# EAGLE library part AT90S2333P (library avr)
MICROCONTROLLER 2 Kbytes FLASH 128 bytes SRAM 128 bytes EEPROM UART 6-channel 10-bit ADC
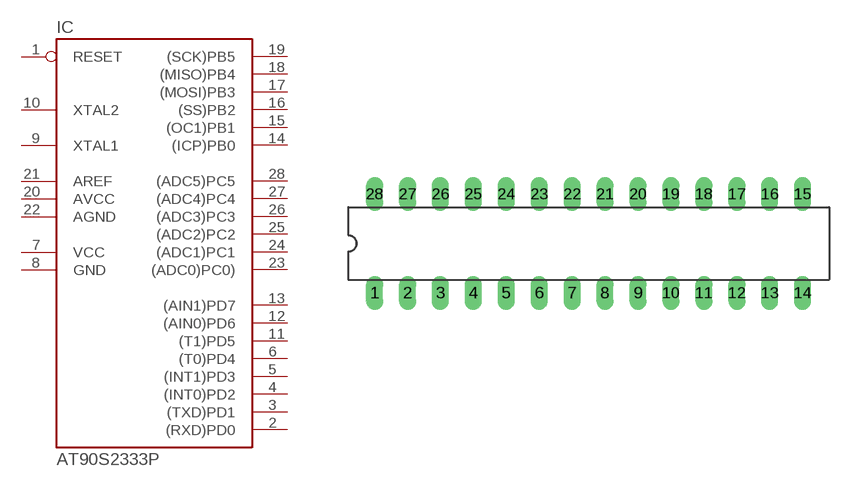
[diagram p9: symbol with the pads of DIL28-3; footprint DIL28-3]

Designator prefix IC

## AT90S2333P  [DIL28-3]
1  RESET  in
2  (RXD)PD0
3  (TXD)PD1
4  (INT0)PD2
5  (INT1)PD3
6  (T0)PD4
7  VCC  pwr
8  GND  pwr
9  XTAL1
10  XTAL2
11  (T1)PD5
12  (AIN0)PD6
13  (AIN1)PD7
14  (ICP)PB0
15  (OC1)PB1
16  (SS)PB2
17  (MOSI)PB3
18  (MISO)PB4
19  (SCK)PB5
20  AVCC  pwr
21  AREF  pwr
22  AGND  pwr
23  (ADC0)PC0)
24  (ADC1)PC1
25  (ADC2)PC2
26  (ADC3)PC3
27  (ADC4)PC4
28  (ADC5)PC5

## Footprint DIL28-3 (pad centres in mm)
Dual In Line 0.3 inch
drill 0.813 long: 1 -16.51,-3.81; 2 -13.97,-3.81; 3 -11.43,-3.81; 4 -8.89,-3.81; 5 -6.35,-3.81; 6 -3.81,-3.81; 7 -1.27,-3.81; 8 1.27,-3.81; 9 3.81,-3.81; 10 6.35,-3.81; 11 8.89,-3.81; 12 11.43,-3.81; 13 13.97,-3.81; 14 16.51,-3.81; 15 16.51,3.81; 16 13.97,3.81; 17 11.43,3.81; 18 8.89,3.81; 19 6.35,3.81; 20 3.81,3.81; 21 1.27,3.81; 22 -1.27,3.81; 23 -3.81,3.81; 24 -6.35,3.81; 25 -8.89,3.81; 26 -11.43,3.81; 27 -13.97,3.81; 28 -16.51,3.81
